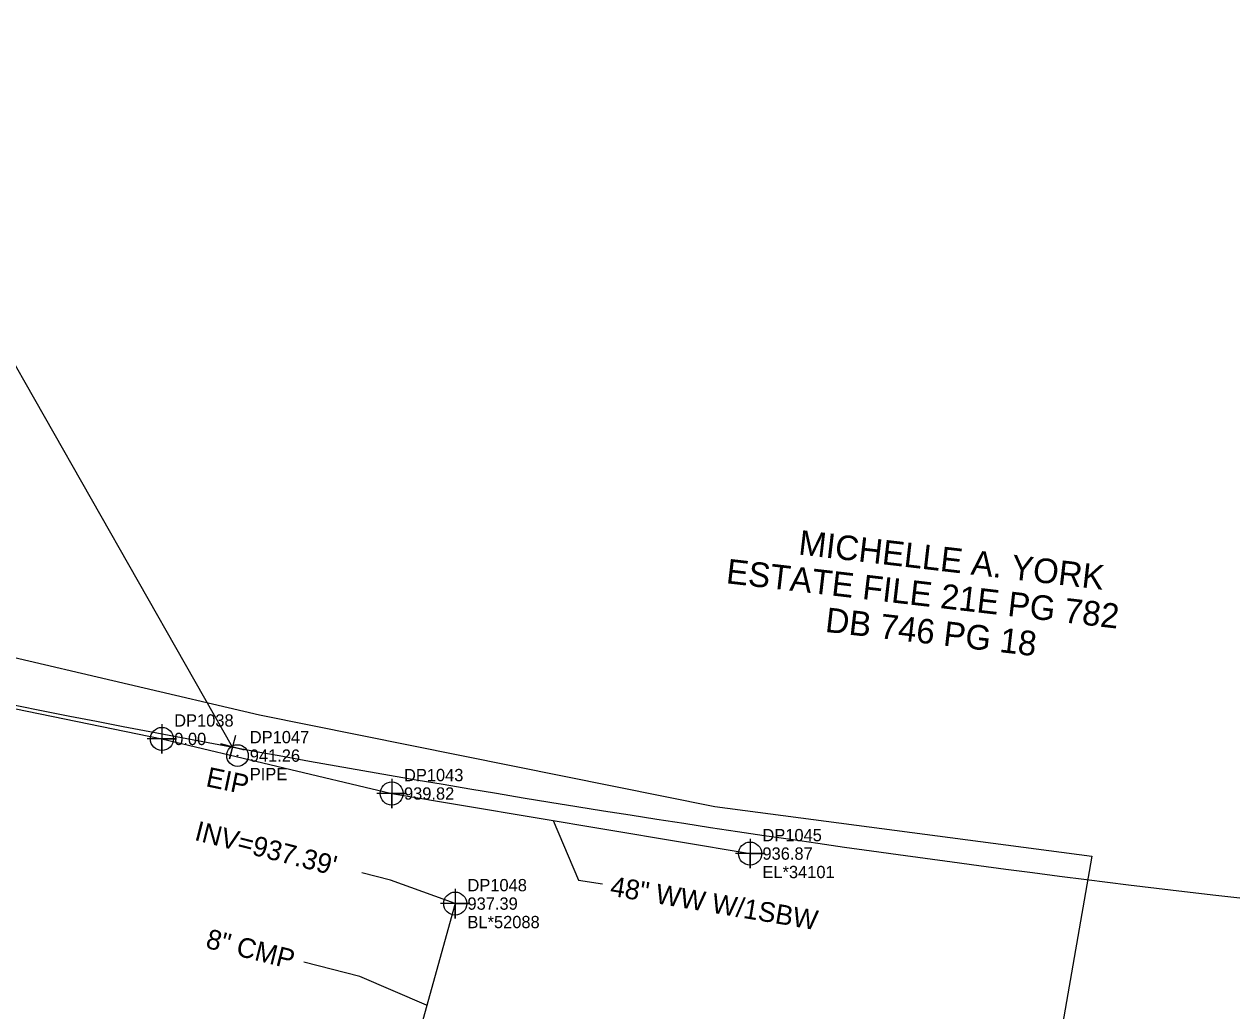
# Model space of a CAD drawing. Extents: x 1182322 to 1186765, y 572295 to 575411.
# Drawn here: x 1185843 to 1186088.5, y 573820.6 to 574021.2 of the extents above; entities that cross this region are included whole.
import ezdxf

# ---------------------------------------------------------------- set-up
doc = ezdxf.new("R2010")
doc.units = 0
for name, color, linetype in [('Exist Guardrail', 7, 'Continuous'), ('Exist Other Culture Fence Line', 7, 'Continuous'), ('Exist Other Culture Fence Line Cogo Comment', 7, 'Continuous'), ('Exist Other Culture Fence Line Cogo Elevation', 7, 'Continuous'), ('Exist Other Culture Fence Line Cogo Number', 7, 'Continuous'), ('Exist Other Culture Fence Line Cogo Point CELL', 7, 'Continuous'), ('Exist Other Culture Fence Line Leader', 7, 'Continuous'), ('Exist Other Culture Fence Line Text', 7, 'Continuous'), ('Exist Property Corner CELL', 7, 'Continuous'), ('Exist Property Deed Book Text', 7, 'Continuous'), ('Exist Property Iron Pin CELL', 7, 'Continuous'), ('Exist Property Iron Pin Cogo Comment', 7, 'Continuous'), ('Exist Property Iron Pin Cogo Elevation', 7, 'Continuous'), ('Exist Property Iron Pin Cogo Number', 7, 'Continuous'), ('Exist Property Iron Pin Text', 7, 'Continuous'), ('Exist Property Line', 7, 'Continuous'), ('Exist Property Owner Text', 7, 'Continuous'), ('Exist Right of Way Line', 7, 'Continuous'), ('Exist Structure Minor Pipes CMP 8 Inch', 7, 'Continuous'), ('Exist Structure Minor Pipes CMP 8 Inch Cogo Comment', 7, 'Continuous'), ('Exist Structure Minor Pipes CMP 8 Inch Cogo Elevation', 7, 'Continuous'), ('Exist Structure Minor Pipes CMP 8 Inch Cogo Number', 7, 'Continuous'), ('Exist Structure Minor Pipes CMP 8 Inch Cogo Point CELL', 7, 'Continuous'), ('Exist Structure Minor Pipes CMP 8 Inch Invert', 7, 'Continuous'), ('Exist Structure Minor Pipes CMP 8 Inch Leader', 7, 'Continuous'), ('Exist Structure Minor Pipes CMP 8 Inch Text', 7, 'Continuous'), ('Sheet Layout Plan Border', 7, 'Continuous')]:
    doc.layers.add(name, color=color, linetype=linetype)

msp = doc.modelspace()

# ---------------------------------------------------------------- linework, layer by layer
at = {"layer": 'Exist Guardrail'}
msp.add_spline([(1185390.3, 573940.07), (1185437.01, 573922.28), (1185484.33, 573906.54), (1185526.22, 573893.43), (1185574.13, 573879.46), (1185622.33, 573866.54), (1185670.88, 573853.88), (1185719.13, 573841.46), (1185767.43, 573829.33), (1185816.18, 573817.9), (1185864.94, 573807.26), (1185913.93, 573797.57), (1185963.25, 573788.74), (1186012.41, 573780.34), (1186049.41, 573774.82)], degree=3, dxfattribs=at)
at = {"layer": 'Exist Other Culture Fence Line'}
msp.add_lwpolyline([(1185576.16, 573944.72), (1185627.61, 573931.32), (1185657.39, 573922.77), (1185698.44, 573912.89), (1185744.14, 573901.13), (1185780.46, 573894.53), (1185823.78, 573885.57), (1185871, 573875.87), (1185917.72, 573864.77), (1185990.6, 573852.56)], dxfattribs=at)
at = {"layer": 'Exist Other Culture Fence Line Cogo Point CELL'}
for points in [[(1185871, 573878.87), (1185871, 573872.87), (1185871, 573875.87), (1185874, 573875.87), (1185868, 573875.87)], [(1185917.72, 573867.77), (1185917.72, 573861.77), (1185917.72, 573864.77), (1185920.72, 573864.77), (1185914.72, 573864.77)], [(1185990.6, 573855.56), (1185990.6, 573849.56), (1185990.6, 573852.56), (1185993.6, 573852.56), (1185987.6, 573852.56)]]:
    msp.add_lwpolyline(points, dxfattribs=at)
for centre in [(1185871, 573875.87), (1185917.72, 573864.77), (1185990.6, 573852.56)]:
    msp.add_circle(centre, 2.34, dxfattribs=at)
at = {"layer": 'Exist Other Culture Fence Line Leader'}
msp.add_lwpolyline([(1185950.54, 573859.27), (1185955.69, 573847.18), (1185960.56, 573846.38)], dxfattribs=at)
at = {"layer": 'Exist Property Corner CELL'}
msp.add_line((1185885.38, 573874.21), (1185885.38, 573874.21), dxfattribs=at)
msp.add_lwpolyline([(1185887.8, 573873.55), (1185882.97, 573874.87), (1185885.38, 573874.21), (1185884.72, 573871.8), (1185886.05, 573876.62)], dxfattribs=at)
at = {"layer": 'Exist Property Iron Pin CELL'}
for radius in [2.2, 0.0707]:
    msp.add_circle((1185886.37, 573872.48), radius, dxfattribs=at)
at = {"layer": 'Exist Property Line'}
msp.add_line((1185885.38, 573874.21), (1185478.65, 574588.33), dxfattribs=at)
at = {"layer": 'Exist Right of Way Line'}
for centre, radius, start, end in [((1186442.72, 576894.22), 3071, 256.24258, 262.82154), ((1186401.9, 576570.15), 2744.37, 262.82154, 274.34174)]:
    msp.add_arc(centre, radius, start, end, dxfattribs=at)
at = {"layer": 'Exist Structure Minor Pipes CMP 8 Inch'}
msp.add_line((1185930.63, 573842.39), (1185918.39, 573798.56), dxfattribs=at)
at = {"layer": 'Exist Structure Minor Pipes CMP 8 Inch Cogo Point CELL'}
msp.add_lwpolyline([(1185930.63, 573845.39), (1185930.63, 573839.39), (1185930.63, 573842.39), (1185933.63, 573842.39), (1185927.63, 573842.39)], dxfattribs=at)
msp.add_circle((1185930.63, 573842.39), 2.34, dxfattribs=at)
at = {"layer": 'Exist Structure Minor Pipes CMP 8 Inch Leader'}
for points in [[(1185930.63, 573842.39), (1185917.48, 573847.17), (1185911.67, 573848.66)], [(1185924.79, 573821.76), (1185911.25, 573827.59), (1185899.88, 573830.5)]]:
    msp.add_lwpolyline(points, dxfattribs=at)
at = {"layer": 'Sheet Layout Plan Border'}
for p, q in [((1185598.72, 573949.14), (1185890.83, 573880.78)), ((1185890.83, 573880.78), (1185983.41, 573862.14)), ((1185983.41, 573862.14), (1186060.04, 573852.02)), ((1186060.04, 573852.02), (1186015.29, 573593.97))]:
    msp.add_line(p, q, dxfattribs=at)

# ---------------------------------------------------------------- texts
at = {"layer": 'Exist Other Culture Fence Line Cogo Comment'}
msp.add_text('EL*34101', height=2.5, dxfattribs=at).set_placement((1185993.1, 573847.56))
at = {"layer": 'Exist Other Culture Fence Line Cogo Elevation'}
for s, p in [('0.00', (1185873.5, 573874.62)), ('939.82', (1185920.22, 573863.52)), ('936.87', (1185993.1, 573851.31))]:
    msp.add_text(s, height=2.5, dxfattribs=at).set_placement(p)
at = {"layer": 'Exist Other Culture Fence Line Cogo Number'}
for s, p in [('DP1038', (1185873.5, 573878.37)), ('DP1043', (1185920.22, 573867.27)), ('DP1045', (1185993.1, 573855.06))]:
    msp.add_text(s, height=2.5, dxfattribs=at).set_placement(p)
at = {"layer": 'Exist Other Culture Fence Line Text'}
msp.add_text('48" WW W/1SBW', height=4, rotation=350.4869, dxfattribs=at).set_placement((1185961.96, 573844.03))
at = {"layer": 'Exist Property Deed Book Text'}
for s, p in [('ESTATE FILE 21E PG 782', (1185985.57, 573907.54)), ('DB 746 PG 18', (1186005.71, 573897.65))]:
    msp.add_text(s, height=5, rotation=353.3768, dxfattribs=at).set_placement(p)
at = {"layer": 'Exist Property Iron Pin Cogo Comment'}
msp.add_text('PIPE', height=2.5, dxfattribs=at).set_placement((1185888.87, 573867.48))
at = {"layer": 'Exist Property Iron Pin Cogo Elevation'}
msp.add_text('941.26', height=2.5, dxfattribs=at).set_placement((1185888.87, 573871.23))
at = {"layer": 'Exist Property Iron Pin Cogo Number'}
msp.add_text('DP1047', height=2.5, dxfattribs=at).set_placement((1185888.87, 573874.98))
at = {"layer": 'Exist Property Iron Pin Text'}
msp.add_text('EIP', height=4, rotation=348.1029, dxfattribs=at).set_placement((1185879.76, 573866.28))
at = {"layer": 'Exist Property Owner Text'}
msp.add_text('MICHELLE A. YORK', height=5, rotation=353.3768, dxfattribs=at).set_placement((1186000.28, 573913.38))
at = {"layer": 'Exist Structure Minor Pipes CMP 8 Inch Cogo Comment'}
msp.add_text('BL*52088', height=2.5, dxfattribs=at).set_placement((1185933.13, 573837.39))
at = {"layer": 'Exist Structure Minor Pipes CMP 8 Inch Cogo Elevation'}
msp.add_text('937.39', height=2.5, dxfattribs=at).set_placement((1185933.13, 573841.14))
at = {"layer": 'Exist Structure Minor Pipes CMP 8 Inch Cogo Number'}
msp.add_text('DP1048', height=2.5, dxfattribs=at).set_placement((1185933.13, 573844.89))
at = {"layer": 'Exist Structure Minor Pipes CMP 8 Inch Invert'}
msp.add_text("INV=937.39'", height=4, rotation=345.6405, dxfattribs=at).set_placement((1185877.44, 573855.36))
at = {"layer": 'Exist Structure Minor Pipes CMP 8 Inch Text'}
msp.add_text('8" CMP', height=4, rotation=345.8611, dxfattribs=at).set_placement((1185879.71, 573833.45))

doc.saveas('drawing.dxf')
